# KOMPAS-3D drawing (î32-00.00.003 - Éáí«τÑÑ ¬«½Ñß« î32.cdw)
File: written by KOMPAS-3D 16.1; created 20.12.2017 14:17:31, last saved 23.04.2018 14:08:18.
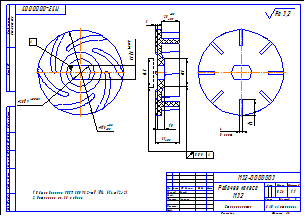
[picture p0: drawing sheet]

Sheet 1: A3, landscape

Title block, sheet 1: name: Рабочее колесо / М32; designation: М32-00.00.003; mass: 0,26; scale: 1:1; sheets: 1; organisation: ЗАО «Астерион»; sheet format: A3; stored path: D:\Отработать\Магна 40\Чертежи\М40-00.00.003 - Рабочее колесо М40.cdw; drawn by: Милов; technical control: Лучихин

Views: Вид 1, Проекционный вид 2, Проекционный вид 3
Referenced files in D:\Отработать\Магна 40\3Д\: М40-00.00.003 - Рабочее колесо М40.m3d
Referenced files in Z:\Магна\Магна Ins\Магна ins 32\: М32-00.00.003 - Рабочее колесо М32.m3d
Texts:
  Стеклопластик
  Общие допуски ГОСТ 30893.2-mK (H14, h14,  t2/2).
  Остальное см. 3Д модель.
  Ra 3,2
Dimensions and other numbers on the sheet: 20; 28; 118; 10; 40; 38; 0,05; 25; 3; 33; 14; 4; 8 мест; 1:1; 1; 0,26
